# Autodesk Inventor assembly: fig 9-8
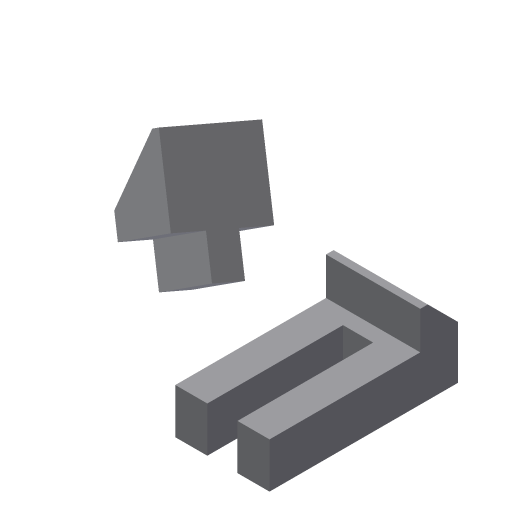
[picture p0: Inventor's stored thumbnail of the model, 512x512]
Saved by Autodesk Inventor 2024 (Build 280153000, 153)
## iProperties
Shininess: 64.0
Length Units: 11269
Angle Units: 11279
Time Units: 11290
Mass Units: 11283
Length Display Precision: 3
Angle Display Precision: 2
Created: 2002-01
Part Number: fig 9-8
Document SubType Name: Assembly
Designer: ***
Density: 0.0
Volumn: 0.0
Area: 0.0
PropertySet Name: Model Information
Control State: 0
Master: False
Checked Out: False
Author: ***
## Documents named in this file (3)
- D:\PROJECTS\Project 2023\RESOURCES INVENTOR 2024\RESOURCES INVENTOR 2024\Inventor_2023_Part\Inventor_2024_Part\c09_Inv_2024_prt\fig 9-8.iam
- D:\PROJECTS\Project 2023\RESOURCES INVENTOR 2024\RESOURCES INVENTOR 2024\Inventor_2023_Part\Inventor_2024_Part\c09_Inv_2024_prt\Part3.ipt
- D:\PROJECTS\Project 2023\RESOURCES INVENTOR 2024\RESOURCES INVENTOR 2024\Inventor_2023_Part\Inventor_2024_Part\c09_Inv_2024_prt\Part4.ipt
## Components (2 placed, 2 different names)
1. Part3:1
2. Part4:1
